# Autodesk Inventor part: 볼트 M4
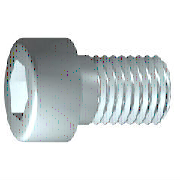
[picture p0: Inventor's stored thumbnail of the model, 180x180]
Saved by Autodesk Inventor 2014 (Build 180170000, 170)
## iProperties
IsCustomPart: 0
Created: 2012-02
Part Number: 볼트 M4
Material: 스테인리스강
Description: 6각 소켓 머리 캡 나사
Document SubType Name: Modeling
Standard: ISO 4762
Designer: mduedu
Standard Revision: Fourth edition 2004-03-01
Standards Organization: ISO
Language: ko-KR
Size Designation: M4 x 10
Categories: <MemberInstance><Categories><Category DisplayName="조임쇠" InternalName="e4da775c-781d-43d5-af7c-5136215cf5a6" Mnemonic="FSTN"><Category DisplayName="볼트" InternalN
Density: 7.75 g/cm^3
Appearance: 반광택
Author: mduedu
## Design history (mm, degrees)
sketch "스케치1"
  geometry: L1 (-1, 0)-(10, 0); L2 (10, 0)-(10, 2); L3 (10, 2)-(1.75, 2); L4 (1.75, 2)-(1.32, 2); L5 (1.32, 2)-(0, 2); L6 (0, 2)-(0, 3.5); L7 (0, 3.5)-(-4, 3.5); L8 (-4, 3.5)-(-4, 1.732); L9 (-4, 1.732)-(-2, 1.732); L10 (-2, 1.732)-(-1, 0); L11 (-6.8, 0)-(12.8, 0) reference; L12 (0, -0.7)-(0, 4.2) reference; L13 (1.75, 2)-(0, 2)
  constraints: 22 end point, 6 parallel, 2 collinear, 2 perpendicular, 1 horizontal, 1 point on line
  dimensions: "d1" = 8.25 distance from line of L3.end L2 (= GEL); "d2" = 0.42952 distance of L4.end L3.end (computed from GAL); "d3" = 4 distance between parallel lines of L8 L6 (= KOH); "d4" = 2 distance of L8.end L9.end (= INTI); "d5" = 60 deg angle of L10 L1; "d6" = 4 diameter of L3 L1 (= GD); "d7" = 4 diameter of L5 L1 (= BDM); "d8" = 3.4641 diameter of L9 L1 (= 1.1547 x SW); "d9" = 7 diameter of L7 L1 (= KOD); "d26" = 10 distance between parallel lines of L12 L2 (= NLG)
revolve "본체" sketch "스케치1" stored, may be unused: angle "d10" = 90 deg
sketch "스케치2"
  geometry: L1 (0, -4.9)-(0, 4.9) reference; L2 (-4.9, 0)-(4.9, 0) reference; L3 (1.732, 0)-(0.866, -1.5); L4 (0.866, -1.5)-(-0.866, -1.5); L5 (-0.866, -1.5)-(-1.732, 0); L6 (-1.732, 0)-(-0.866, 1.5); L7 (-0.866, 1.5)-(0.866, 1.5); L8 (0.866, 1.5)-(1.732, 0); 2 further points
  constraints: 12 end point, 1 coincident, 1 horizontal alignment, 1 point on line, 12 other
extrude "슬롯" join sketch "스케치2" stored distance "d11" = 10; taper "d12" = 0 deg
workplane "Work Plane1"
fillet "Fillet2" dims "d30" = 0.1 (= R)
body "Solid1"
fillet "모깎기1" dims "d17" = 0.4 (= RR)
feature "스레드" dims "d13" = 8.25 (= GEL), "d14" = 0
chamfer "모따기1" distance "d15" = 0.42941 (= -0.5 x SPD + 0.5 x GD); stored, may be unused: second distance "d16" = 0.42941 (= GUL), angle "d27" = 45 deg
other parameters: "GD" = 4 [user parameter; used in 2 equation terms], "NLG" = 10 [user parameter; used in 1 equation term], "GEL" = 8.25 [user parameter; used in 2 equation terms], "KOD" = 7 [user parameter; used in 1 equation term], "KOH" = 4 [user parameter; used in 1 equation term], "INTI" = 2 [user parameter; used in 1 equation term], "GAL" = 0.42941 (= 0.61345 x PTC) [user parameter; used in 1 equation term], "GUL" = 0.42941 (= 0.61345 x PTC) [user parameter; used in 1 equation term], "BDM" = 4 (= NND) [user parameter; used in 1 equation term], "SW" = 3 [user parameter; used in 2 equation terms], "RR" = 0.4 [user parameter; used in 1 equation term], "SPD" = 3.14117 (= NND - 1.2269 x PTC) [user parameter; used in 1 equation term], "d19" = 0, "d28" = 0, "d29" = 0, "R" = 0.1 [user parameter; used in 1 equation term], "TOA" = 30 deg [user parameter], "GD1" = 3.14117 (= THREADDIA - 1.2269 x PTC) [user parameter], "THREADDIA" = 4 [user parameter; used in 1 equation term], "FAWI" = 45 deg [user parameter], "TPU" = 14.28571 (computed from PTC) [user parameter], "PTC" = 0.7 [user parameter; used in 5 equation terms], "NND" = 4 [user parameter; used in 2 equation terms], "E0" = 3.465 (= 1.155 x SW) [user parameter]
